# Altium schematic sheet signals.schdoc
size 306 x 212 mm
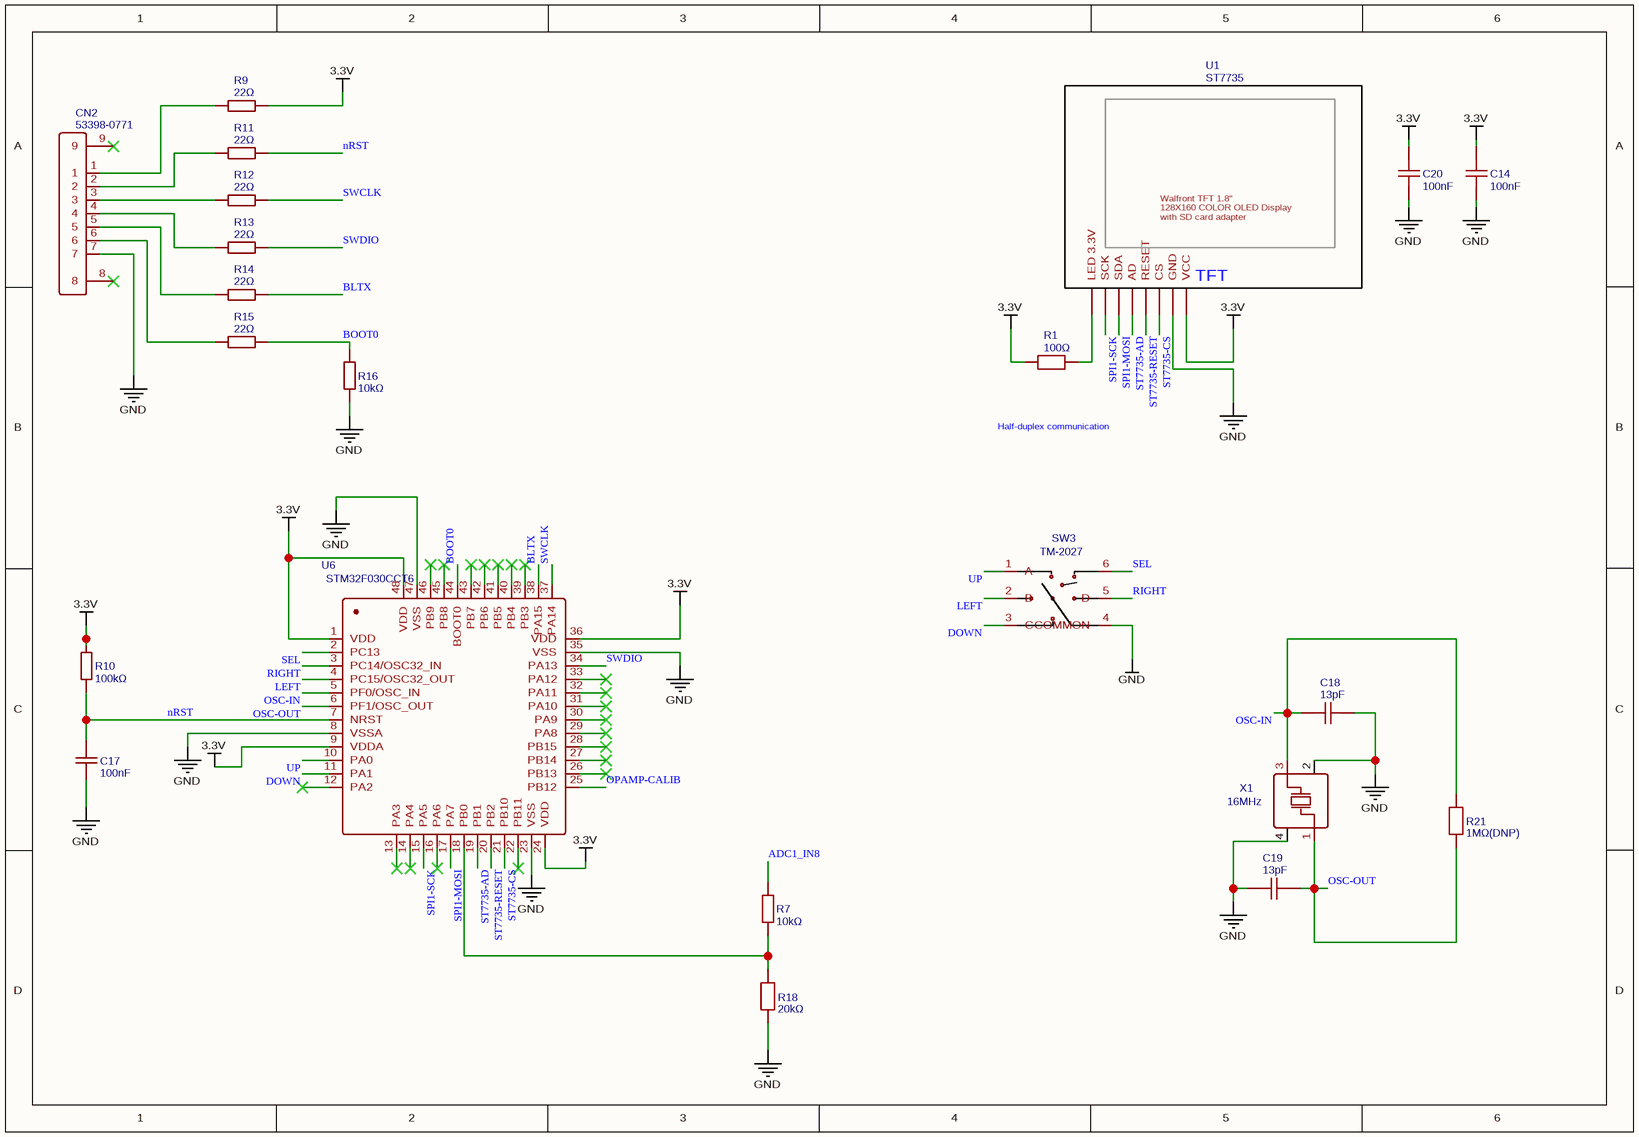
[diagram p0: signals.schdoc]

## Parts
C14  100nF  [C0603]
C17  100nF  [C1206]
C18  13pF  [C0402]
C19  13pF  [C0402]
C20  100nF  [C0603]
CN2  53398-0771  [CONN-SMD_7P-P1.25_53398-0771]
R1  100Ω  [R0603]
R7  10kΩ  [R0603]
R9  22Ω  [R0805]
R10  100kΩ  [R0603]
R11  22Ω  [R0805]
R12  22Ω  [R0805]
R13  22Ω  [R0805]
R14  22Ω  [R0805]
R15  22Ω  [R0805]
R16  10kΩ  [R0603]
R18  20kΩ  [R0603]
R21  1MΩ(DNP)  [R0805]
SW3  TM-2027  [SW-SMD_6P-P2.80-L10.2-W10.2]
U1  ST7735  [LCD ST7735]
U6  STM32F030CCT6  [LQFP-48_L7.0-W7.0-P0.50-LS9.0-BL]
X1  16MHz  [CRYSTAL-SMD_4P-L3.2-W2.5-BL]

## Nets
3.3V: C14.2 C20.2 R1.1 R9.2 R10.1 U1.1(VCC) U6.1(VDD) U6.9(VDDA) U6.24(VDD) U6.36(VDD) U6.48(VDD)
GND: C14.1 C17.1 C18.2 C19.1 C20.1 CN2.7 R16.1 R18.2 SW3.4(COMMON) U1.2(GND) U6.8(VSSA) U6.23(VSS) U6.35(VSS) U6.47(VSS) X1.2(GND) X1.4(GND)
ADC1_IN8: R7.2
BLTX: R14.2 U6.38(PA15)
BOOT0: R15.2 R16.2 U6.44(BOOT0)
DOWN: SW3.3(C) U6.11(PA1)
LEFT: SW3.2(B) U6.4(PC15/OSC32_OUT)
nRST: C17.2 R10.2 R11.2 U6.7(NRST)
OPAMP-CALIB: U6.25(PB12)
OSC-IN: C18.1 R21.2 U6.5(PF0/OSC_IN) X1.3(OSC2)
OSC-OUT: C19.2 R21.1 U6.6(PF1/OSC_OUT) X1.1(OSC1)
RIGHT: SW3.5(D) U6.3(PC14/OSC32_IN)
SEL: SW3.6(E) U6.2(PC13)
SPI1-MOSI: U1.6(SDA) U6.17(PA7)
SPI1-SCK: U1.7(SCK) U6.15(PA5)
ST7735-AD: U1.5(AD) U6.19(PB1)
ST7735-CS: U1.3(CS) U6.21(PB10)
ST7735-RESET: U1.4(RESET) U6.20(PB2)
SWCLK: R12.2 U6.37(PA14)
SWDIO: R13.2 U6.34(PA13)
UP: SW3.1(A) U6.10(PA0)
NetCN2_1: CN2.1 R9.1
NetCN2_2: CN2.2 R11.1
NetCN2_3: CN2.3 R12.1
NetCN2_4: CN2.4 R13.1
NetCN2_5: CN2.5 R14.1
NetCN2_6: CN2.6 R15.1
NetR1_2: R1.2 U1.8(LED_3.3V)
NetR7_1: R7.1 R18.1 U6.18(PB0)

Not connected (* = marked no-connect by the designer): CN2 8* 9*; U6 12(PA2)* 13(PA3)* 14(PA4)* 16(PA6)* 22(PB11)* 26(PB13)* 27(PB14)* 28(PB15)* 29(PA8)* 30(PA9)* 31(PA10)* 32(PA11)* 33(PA12)* 39(PB3)* 40(PB4)* 41(PB5)* 42(PB6)* 43(PB7)* 45(PB8)* 46(PB9)*

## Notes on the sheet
- Half-duplex communication

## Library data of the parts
C14 C20 = 100nF: Manufacturer: FH(风华); Manufacturer Part: 0603B104M250NT; nameAlias: Value; Contributor: LCSC
C17 = 100nF: Manufacturer Part: CL31B104KBCNNNC; Manufacturer: SAMSUNG(三星); nameAlias: Value
C18 C19 = 13pF: Manufacturer: YAGEO(国巨); Manufacturer Part: CC0402FRNPO9BN130; nameAlias: Value; Contributor: LCSC
CN2 = 53398-0771: Manufacturer: MOLEX; Manufacturer Part: 533980771; Contributor: LCSC
R1 = 100Ω: Manufacturer: YAGEO(国巨); Manufacturer Part: RT0603BRC07100RL; Contributor: LCSC; nameAlias: Value
R7 = 10kΩ: Manufacturer: RESI(开步睿思）; Manufacturer Part: PTFR0603B10K0P9; nameAlias: Value; Contributor: LCSC
R9 R11-R15 = 22Ω: Manufacturer: UNI-ROYAL(厚声); Manufacturer Part: 0805W8F220JT5E; nameAlias: Value
R10 = 100kΩ: Manufacturer: UNI-ROYAL(厚声); Manufacturer Part: 0603WAF1003T5E; nameAlias: Value
R16 = 10kΩ: Manufacturer: UNI-ROYAL(厚声); Manufacturer Part: 0603WAF1002T5E; nameAlias: Value
R18 = 20kΩ: Manufacturer: YAGEO(国巨); Manufacturer Part: RT0603CRC0720KL; Contributor: LCSC; nameAlias: Value
R21 = 1MΩ(DNP): Manufacturer: Viking(光颉); Manufacturer Part: AR05BTC1004; nameAlias: Value; Contributor: LCSC
SW3 = TM-2027: Manufacturer: XKB Connectivity(中国星坤); Contributor: LCSC; Package Display: No
U1 = ST7735: Manufacturer Part: st7735 TFT 1.8 160x128; Contributor: andreafato
U6 = STM32F030CCT6: Manufacturer: ST(意法半导体)
X1 = 16MHz: Manufacturer: TAE(雅晶鑫); Manufacturer Part: TAXM16M4RDBCCT2T; nameAlias: Value; Contributor: LCSC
